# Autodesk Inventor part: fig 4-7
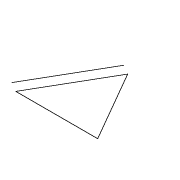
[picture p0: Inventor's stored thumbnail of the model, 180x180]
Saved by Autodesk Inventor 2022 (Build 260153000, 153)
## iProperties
Created: 2005-02
Part Number: fig 4-7
Document SubType Name: Modeling
Designer: CADCIM
Manufacturer: Standard
Standards Organization: Custom
Density: 1 g/cm^3
Material: Generic
Appearance: Default
Author: CADCIM
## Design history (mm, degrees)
sketch "Sketch1"
  geometry: L1 (-3.883, 28.419)-(-24.946, -8.063); L2 (-24.946, -8.063)-(17.18, -8.063); L3 (17.18, -8.063)-(-3.883, 28.419); L4 (-8.847, 31.285)-(-29.909, -5.197)
  constraints: 8 end point, 2 equal length, 1 horizontal, 1 parallel, 1 other
